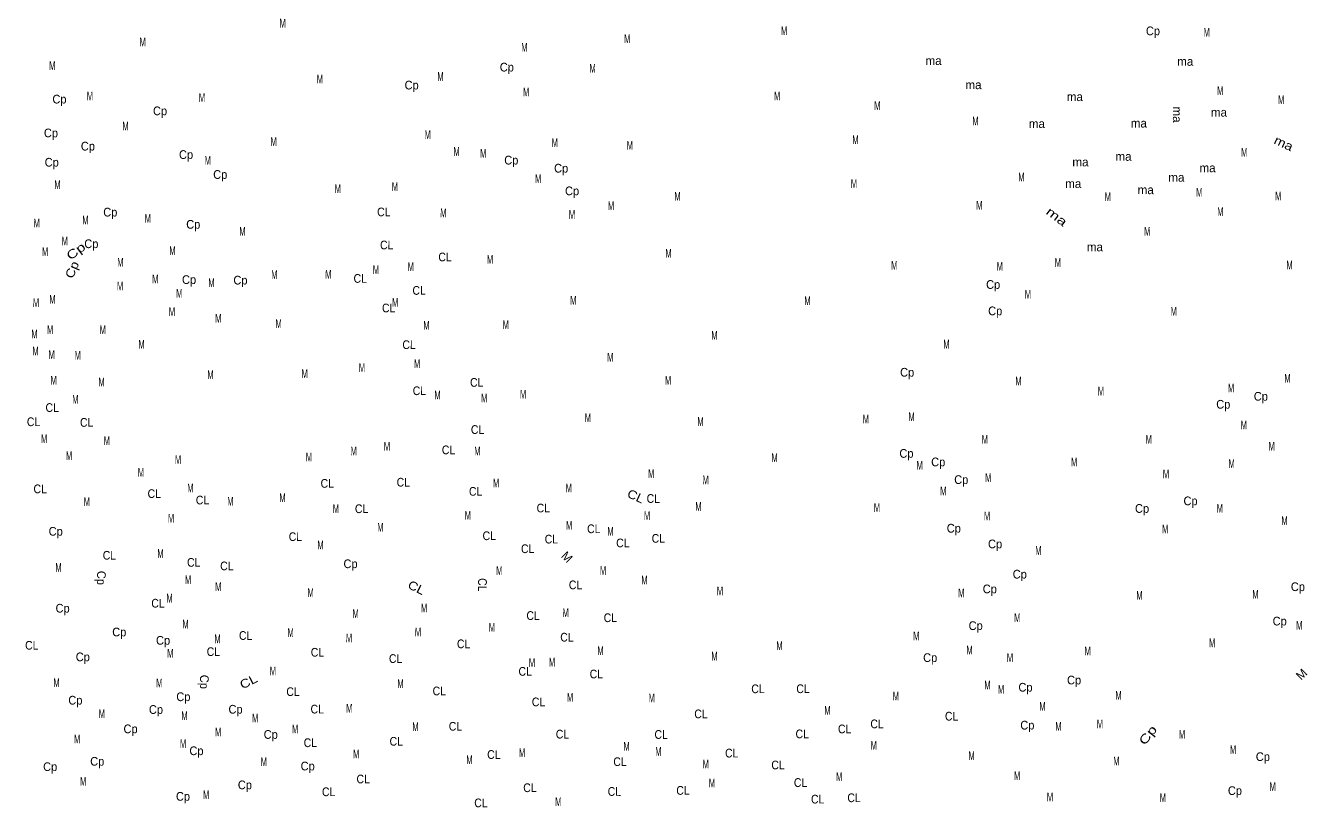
# Model space of a CAD drawing. Extents: x 713577 to 726626, y 7177731 to 7191794.
# Drawn here: x 713655 to 719260, y 7182918 to 7186338 of the extents above; entities that cross this region are included whole.
import ezdxf
from ezdxf.enums import TextEntityAlignment as Align

# ---------------------------------------------------------------- set-up
doc = ezdxf.new("R2010")
doc.units = 0
doc.header["$LTSCALE"] = 15
doc.layers.add('19', color=7, linetype='Continuous')

msp = doc.modelspace()

# ---------------------------------------------------------------- texts
at = {"layer": '19'}
for s, rotation, width, p in [('M', 359.905, 0.65, (714779.16, 7186329.35)), ('M', 359.99, 0.65, (716972.08, 7186296.01)), ('Cp', 359.99, 0.95, (718585.11, 7186295.53)), ('M', 359.99, 0.65, (718820.07, 7186289.81)), ('M', 359.905, 0.65, (714167.03, 7186247.01)), ('M', 359.905, 0.65, (716286.1, 7186261.26)), ('M', 359.905, 0.65, (715836.26, 7186223.86)), ('M', 359.905, 0.65, (713771.9, 7186143.61)), ('Cp', 359.905, 0.95, (715759.5, 7186136.98)), ('M', 359.905, 0.65, (716134.57, 7186132.32)), ('M', 359.905, 0.65, (714941.93, 7186084.8)), ('Cp', 359.905, 0.95, (715343.19, 7186058.48)), ('M', 359.905, 0.65, (715469.3, 7186096.1)), ('M', 359.905, 0.65, (713936.46, 7186010.29)), ('M', 359.905, 0.65, (714426.3, 7186003.39)), ('M', 359.905, 0.65, (715843.95, 7186028.48)), ('M', 359.99, 0.65, (716941.68, 7186011.33)), ('M', 359.99, 0.65, (718879.26, 7186034.47)), ('Cp', 359.905, 0.95, (713803.14, 7185997.05)), ('Cp', 359.905, 0.95, (714242.89, 7185945.67)), ('M', 359.99, 0.65, (717379.75, 7185968.7)), ('M', 359.99, 0.65, (719145.99, 7185994.19)), ('M', 359.99, 0.65, (717808.91, 7185901.66)), ('Cp', 359.905, 0.95, (713765.96, 7185849.13)), ('M', 359.905, 0.65, (714092.04, 7185878.92)), ('M', 359.905, 0.65, (715413.42, 7185842.1)), ('Cp', 359.905, 0.95, (713927.5, 7185791.35)), ('M', 359.905, 0.65, (714739.83, 7185811.48)), ('M', 359.905, 0.65, (715969.25, 7185806.88)), ('M', 359.905, 0.65, (716297.51, 7185795.44)), ('M', 359.99, 0.65, (717284.06, 7185819.28)), ('ma', 334.884, 1.2, (719148.78, 7185805.6)), ('Cp', 359.905, 0.95, (713769.27, 7185720.89)), ('Cp', 359.905, 0.95, (714356.7, 7185754.41)), ('M', 359.905, 0.65, (714451.49, 7185728.93)), ('M', 359.905, 0.65, (715539.82, 7185767.98)), ('M', 359.905, 0.65, (715656.29, 7185759.95)), ('Cp', 359.905, 0.95, (715779.02, 7185730.13)), ('M', 359.99, 0.65, (718984.39, 7185764.23)), ('Cp', 359.905, 0.95, (714506.27, 7185667.29)), ('Cp', 359.905, 0.95, (715996.96, 7185694.82)), ('M', 359.905, 0.65, (713794.44, 7185623.39)), ('M', 359.905, 0.65, (715270.07, 7185614.73)), ('M', 359.905, 0.65, (715896.54, 7185649.59)), ('M', 359.99, 0.65, (717277.51, 7185627.67)), ('M', 359.99, 0.65, (718009.76, 7185656.52)), ('M', 359.905, 0.65, (715020.32, 7185605.52)), ('Cp', 359.905, 0.95, (716044.88, 7185595.68)), ('M', 359.905, 0.65, (716505.91, 7185572.36)), ('M', 359.99, 0.65, (718387.53, 7185570.14)), ('M', 359.99, 0.65, (718787.63, 7185589.39)), ('M', 359.99, 0.65, (719132.95, 7185573.62)), ('Cp', 359.905, 0.95, (714025.44, 7185502.66)), ('CL', 359.905, 0.9, (715221.55, 7185503.57)), ('M', 359.905, 0.65, (715481.9, 7185499.64)), ('M', 359.905, 0.65, (716215.32, 7185530.77)), ('M', 359.99, 0.65, (717825.85, 7185532.22)), ('ma', 322.678, 1.4, (718152.62, 7185486.8)), ('M', 359.99, 0.65, (718879.81, 7185505.11)), ('M', 359.905, 0.65, (713703.75, 7185454.6)), ('M', 359.905, 0.65, (713916.64, 7185468.03)), ('M', 359.905, 0.65, (714189.47, 7185475.14)), ('Cp', 359.905, 0.95, (714388.25, 7185449.17)), ('M', 359.905, 0.65, (716044.33, 7185492.4)), ('M', 359.905, 0.65, (714603.25, 7185419)), ('M', 359.99, 0.65, (718560.15, 7185419.32)), ('M', 359.905, 0.65, (713740.42, 7185330.47)), ('M', 359.905, 0.65, (713826.41, 7185377.13)), ('Cp', 36.789, 1.35, (713886.27, 7185335.83)), ('Cp', 359.905, 0.95, (713942.44, 7185364.44)), ('M', 359.905, 0.65, (714297.27, 7185334.55)), ('CL', 359.905, 0.9, (715234.45, 7185358.96)), ('M', 359.905, 0.65, (714069.58, 7185283.31)), ('CL', 359.905, 0.9, (715489.23, 7185306.61)), ('M', 359.905, 0.65, (715686.21, 7185295.65)), ('M', 359.905, 0.65, (716466.63, 7185322.6)), ('M', 359.99, 0.65, (718169.35, 7185282.42)), ('Cp', 66.992, 1.15, (713875.77, 7185262.42)), ('M', 359.905, 0.65, (714742.93, 7185229.78)), ('M', 359.905, 0.65, (714978.98, 7185230.51)), ('M', 359.905, 0.65, (715187.07, 7185251.32)), ('M', 359.905, 0.65, (715339.32, 7185264.67)), ('M', 359.99, 0.65, (717453.85, 7185269.68)), ('M', 359.99, 0.65, (717915.16, 7185265.87)), ('M', 359.99, 0.65, (719182.26, 7185270.87)), ('M', 359.905, 0.65, (714068.11, 7185179.07)), ('M', 359.905, 0.65, (714222.37, 7185209.97)), ('Cp', 359.905, 0.95, (714369.9, 7185207.48)), ('M', 359.905, 0.65, (714467.91, 7185193.85)), ('Cp', 359.905, 0.95, (714594.62, 7185205.18)), ('CL', 359.905, 0.9, (715118.48, 7185212.65)), ('CL', 359.905, 0.9, (715376.03, 7185160.29)), ('Cp', 359.99, 0.95, (717886.24, 7185186.14)), ('M', 359.905, 0.65, (713700.63, 7185106.53)), ('M', 359.905, 0.65, (713772.49, 7185121.8)), ('M', 359.905, 0.65, (714327.1, 7185147.28)), ('M', 359.905, 0.65, (715271.29, 7185107.64)), ('M', 359.905, 0.65, (716050.35, 7185116.65)), ('M', 359.99, 0.65, (717074.13, 7185115.03)), ('M', 359.99, 0.65, (718038.37, 7185143.56)), ('M', 359.905, 0.65, (714295.16, 7185067.07)), ('CL', 359.905, 0.9, (715242.68, 7185083.44)), ('Cp', 359.99, 0.95, (717895.12, 7185070.68)), ('M', 359.99, 0.65, (718675.72, 7185068.93)), ('M', 359.905, 0.65, (714497.77, 7185037.83)), ('M', 359.905, 0.65, (714761.51, 7185014.47)), ('M', 359.905, 0.65, (715407.99, 7185007.75)), ('M', 359.905, 0.65, (715754.83, 7185010.83)), ('M', 359.905, 0.65, (713693.91, 7184969.73)), ('M', 359.905, 0.65, (713762.35, 7184989.11)), ('M', 359.905, 0.65, (713992.38, 7184988.17)), ('M', 359.905, 0.65, (716667.36, 7184964.14)), ('M', 359.905, 0.65, (713698.57, 7184895.16)), ('M', 359.905, 0.65, (714162.04, 7184925.1)), ('CL', 359.905, 0.9, (715332.12, 7184922.83)), ('M', 359.99, 0.65, (717681.88, 7184925.15)), ('M', 359.905, 0.65, (713769.01, 7184879.31)), ('M', 359.905, 0.65, (713882.9, 7184876.73)), ('M', 359.905, 0.65, (715367.18, 7184840.05)), ('M', 359.905, 0.65, (716212.06, 7184867.88)), ('M', 359.905, 0.65, (713777.71, 7184767.45)), ('M', 359.905, 0.65, (714463.47, 7184792.05)), ('M', 359.905, 0.65, (714875.43, 7184795.68)), ('M', 359.905, 0.65, (715125.96, 7184822.18)), ('Cp', 359.99, 0.95, (717510.11, 7184802.23)), ('M', 359.99, 0.65, (719173.28, 7184776.27)), ('M', 359.905, 0.65, (713987.35, 7184759.95)), ('CL', 359.905, 0.9, (715377.3, 7184721.43)), ('CL', 359.905, 0.9, (715627.85, 7184757.89)), ('M', 359.905, 0.65, (716464.71, 7184766.8)), ('M', 359.99, 0.65, (717996.78, 7184763.98)), ('M', 359.99, 0.65, (718357.6, 7184719.56)), ('M', 359.99, 0.65, (718926.8, 7184733.54)), ('M', 359.905, 0.65, (713872.66, 7184683.5)), ('M', 359.905, 0.65, (715456.32, 7184702.69)), ('M', 359.905, 0.65, (715660.62, 7184689.73)), ('M', 359.905, 0.65, (715830.41, 7184706.39)), ('Cp', 359.99, 0.95, (718892.57, 7184662.14)), ('Cp', 359.99, 0.95, (719056.78, 7184696.99)), ('CL', 359.905, 0.9, (713771.37, 7184647.75)), ('M', 359.905, 0.65, (716113.95, 7184603.27)), ('M', 359.99, 0.65, (717529.55, 7184607.96)), ('CL', 359.905, 0.9, (713689.86, 7184585.64)), ('CL', 359.905, 0.9, (713922.09, 7184582.86)), ('CL', 359.905, 0.9, (715631.49, 7184551.58)), ('M', 359.905, 0.65, (716606.27, 7184586.84)), ('M', 359.99, 0.65, (717329.7, 7184597.74)), ('M', 359.99, 0.65, (718982.39, 7184571.95)), ('M', 359.905, 0.65, (713736.25, 7184511.34)), ('M', 359.905, 0.65, (714010.2, 7184503.36)), ('M', 359.99, 0.65, (717850.06, 7184508.67)), ('M', 359.99, 0.65, (718566.64, 7184509.18)), ('M', 359.905, 0.65, (713845.23, 7184436.94)), ('M', 359.905, 0.65, (714894.09, 7184432.2)), ('M', 359.905, 0.65, (715089.81, 7184458.13)), ('M', 359.905, 0.65, (715235.36, 7184477.82)), ('CL', 359.905, 0.9, (715504.44, 7184462.75)), ('M', 359.905, 0.65, (715630.66, 7184457.56)), ('Cp', 359.99, 0.95, (717507.08, 7184447.28)), ('M', 359.99, 0.65, (719104.13, 7184478.81)), ('M', 359.905, 0.65, (714321.66, 7184420.2)), ('M', 359.99, 0.65, (716930.46, 7184428.61)), ('M', 359.99, 0.65, (717564.86, 7184394.82)), ('Cp', 359.99, 0.95, (717645.95, 7184409.98)), ('M', 359.99, 0.65, (718240.63, 7184409.85)), ('M', 359.99, 0.65, (718929.05, 7184402.82)), ('M', 359.905, 0.65, (714159.43, 7184363.91)), ('CL', 359.905, 0.9, (715306.87, 7184321.22)), ('M', 359.905, 0.65, (716390.95, 7184359.29)), ('M', 359.905, 0.65, (716629.1, 7184331.66)), ('Cp', 359.99, 0.95, (717746.68, 7184332.61)), ('M', 359.99, 0.65, (717864.82, 7184341.8)), ('M', 359.99, 0.65, (718642.09, 7184357.13)), ('CL', 359.905, 0.9, (713718.79, 7184292.13)), ('CL', 359.905, 0.9, (714217.72, 7184271.36)), ('M', 359.905, 0.65, (714375.61, 7184295.86)), ('CL', 359.905, 0.9, (714974.31, 7184316.13)), ('CL', 359.905, 0.9, (715623.07, 7184281.17)), ('M', 359.905, 0.65, (715712.49, 7184318.23)), ('M', 359.905, 0.65, (716030.39, 7184296.44)), ('CL', 335.458, 1.15, (716315.71, 7184261.85)), ('M', 359.99, 0.65, (717668.42, 7184282.32)), ('M', 359.905, 0.65, (713922.88, 7184236.38)), ('CL', 359.905, 0.9, (714428.69, 7184243.28)), ('M', 359.905, 0.65, (714550.59, 7184238.09)), ('M', 359.905, 0.65, (714778.52, 7184253.33)), ('CL', 359.905, 0.9, (715918.96, 7184208.25)), ('CL', 359.905, 0.9, (716400.08, 7184249.98)), ('M', 359.905, 0.65, (716597.35, 7184215.1)), ('M', 359.99, 0.65, (717378.12, 7184210.45)), ('Cp', 359.99, 0.95, (718537.42, 7184206.43)), ('Cp', 359.99, 0.95, (718749.35, 7184239.63)), ('M', 359.99, 0.65, (718877.35, 7184207.69)), ('M', 359.905, 0.65, (714291.12, 7184163.6)), ('M', 359.905, 0.65, (715011.99, 7184205.77)), ('CL', 359.905, 0.9, (715124.29, 7184205.25)), ('M', 359.905, 0.65, (715589, 7184176.91)), ('M', 359.905, 0.65, (716372.7, 7184175.27)), ('M', 359.99, 0.65, (717859.53, 7184173.32)), ('M', 359.99, 0.65, (719160.34, 7184153.34)), ('Cp', 359.905, 0.95, (713786.73, 7184106.52)), ('M', 359.905, 0.65, (715206.53, 7184124.38)), ('M', 359.905, 0.65, (716032.11, 7184132.65)), ('CL', 359.905, 0.9, (716139.73, 7184117.52)), ('M', 359.905, 0.65, (716212.79, 7184106.77)), ('Cp', 359.99, 0.95, (717714.18, 7184120.01)), ('M', 359.99, 0.65, (718638.76, 7184117.24)), ('CL', 359.905, 0.9, (714835.06, 7184083.14)), ('M', 359.905, 0.65, (714944.62, 7184047.08)), ('CL', 359.905, 0.9, (715682.55, 7184087.05)), ('CL', 359.905, 0.9, (715954.28, 7184072.32)), ('CL', 359.905, 0.9, (716266.87, 7184055.52)), ('CL', 359.905, 0.9, (716422.05, 7184075.53)), ('Cp', 359.99, 0.95, (717894.72, 7184051.23)), ('CL', 359.905, 0.9, (714021.69, 7184001.59)), ('M', 359.905, 0.65, (714244.69, 7184009.43)), ('CL', 359.905, 0.9, (715850.56, 7184030.3)), ('M', 359.99, 0.65, (718083.93, 7184022.56)), ('M', 359.905, 0.65, (713798.84, 7183948.23)), ('CL', 359.905, 0.9, (714390.34, 7183970.54)), ('CL', 359.905, 0.9, (714535.18, 7183955.07)), ('Cp', 359.905, 0.95, (715076.04, 7183964.47)), ('M', 359.905, 0.65, (715726.47, 7183934.82)), ('M', 359.905, 0.65, (716180.28, 7183935.07)), ('Cp', 270, 0.95, (713967.56, 7183921.7)), ('M', 359.905, 0.65, (714365.58, 7183894.65)), ('CL', 270, 0.9, (715633.95, 7183891.49)), ('CL', 359.905, 0.9, (716059.93, 7183872.15)), ('M', 359.905, 0.65, (716361.27, 7183893.24)), ('Cp', 359.99, 0.95, (718002.63, 7183918.92)), ('M', 359.905, 0.65, (714497.81, 7183863.77)), ('M', 359.905, 0.65, (714901.42, 7183838.52)), ('CL', 333.778, 1.15, (715355.93, 7183862.49)), ('M', 359.99, 0.65, (716691.58, 7183845.73)), ('M', 359.99, 0.65, (717747.13, 7183837.32)), ('Cp', 359.99, 0.95, (717871.49, 7183854.43)), ('M', 359.99, 0.65, (718525.84, 7183826.03)), ('M', 359.99, 0.65, (719033.26, 7183830.88)), ('Cp', 359.99, 0.95, (719218.86, 7183864.08)), ('Cp', 359.905, 0.95, (713816.95, 7183769.93)), ('CL', 359.905, 0.9, (714234.08, 7183791.92)), ('M', 359.905, 0.65, (714284.73, 7183814.06)), ('M', 359.905, 0.65, (715397.64, 7183770.92)), ('M', 359.905, 0.65, (715098.27, 7183746.83)), ('CL', 359.905, 0.9, (715874.33, 7183737.9)), ('M', 359.905, 0.65, (716016.86, 7183750.29)), ('CL', 359.905, 0.9, (716212.18, 7183728.37)), ('M', 359.99, 0.65, (717991.74, 7183728.39)), ('Cp', 359.99, 0.95, (719139.2, 7183713.71)), ('Cp', 359.905, 0.95, (714064.72, 7183665.94)), ('M', 359.905, 0.65, (714354.65, 7183700.39)), ('CL', 359.905, 0.9, (714617.26, 7183650.71)), ('M', 359.905, 0.65, (714813.94, 7183663.72)), ('M', 359.905, 0.65, (715371.1, 7183665.87)), ('M', 359.905, 0.65, (715694.35, 7183686.54)), ('M', 359.99, 0.65, (717550.22, 7183648.97)), ('Cp', 359.99, 0.95, (717809.77, 7183693.79)), ('M', 359.99, 0.65, (719225.09, 7183694.94)), ('CL', 359.905, 0.9, (713682.1, 7183607.85)), ('Cp', 359.905, 0.95, (714256.21, 7183629.5)), ('M', 359.905, 0.65, (714494.44, 7183636.2)), ('M', 359.905, 0.65, (715069.39, 7183639.7)), ('CL', 359.905, 0.9, (715570.43, 7183614.24)), ('CL', 359.905, 0.9, (716022.34, 7183643.31)), ('M', 359.99, 0.65, (716951.81, 7183605.87)), ('M', 359.99, 0.65, (718844.01, 7183618.66)), ('Cp', 359.905, 0.95, (713905.13, 7183557.17)), ('M', 359.905, 0.65, (714287.93, 7183572.58)), ('CL', 359.905, 0.9, (714476.23, 7183580.14)), ('CL', 359.905, 0.9, (714931.46, 7183577.33)), ('CL', 359.905, 0.9, (715273.1, 7183549.75)), ('M', 359.905, 0.65, (716169.07, 7183584.93)), ('M', 359.99, 0.65, (716667.45, 7183560.39)), ('Cp', 359.99, 0.95, (717610.83, 7183553.96)), ('M', 359.99, 0.65, (717783.1, 7183586.92)), ('M', 359.99, 0.65, (717959.79, 7183553.66)), ('M', 359.99, 0.65, (718299.39, 7183582.56)), ('M', 359.905, 0.65, (714736.7, 7183495.23)), ('CL', 359.905, 0.9, (715839.75, 7183493.74)), ('M', 359.905, 0.65, (715869.56, 7183531.66)), ('M', 359.905, 0.65, (715957.36, 7183534.12)), ('CL', 359.905, 0.9, (716150.97, 7183482.3)), ('M', 359.905, 0.65, (713790.27, 7183444.49)), ('M', 359.905, 0.65, (714239.66, 7183443.41)), ('Cp', 270, 0.95, (714417.86, 7183466.92)), ('CL', 26.919, 1.2, (714638.55, 7183451.23)), ('M', 359.905, 0.65, (715294.46, 7183440.26)), ('M', 359.99, 0.65, (717861.25, 7183433.84)), ('Cp', 359.99, 0.95, (718027.55, 7183424.32)), ('Cp', 359.99, 0.95, (718240.14, 7183455.88)), ('Cp', 359.905, 0.95, (713872.66, 7183367.66)), ('Cp', 359.905, 0.95, (714344.95, 7183382.79)), ('CL', 359.905, 0.9, (714824.46, 7183405.13)), ('CL', 359.905, 0.9, (715464.06, 7183408.17)), ('M', 359.905, 0.65, (716036.21, 7183380.2)), ('M', 359.905, 0.65, (716392.98, 7183377.92)), ('CL', 359.99, 0.9, (716857.7, 7183417.54)), ('CL', 359.99, 0.9, (717054.64, 7183417.84)), ('M', 359.99, 0.65, (717460.77, 7183385.42)), ('M', 359.99, 0.65, (717920.93, 7183415.79)), ('M', 359.99, 0.65, (718434.61, 7183389.04)), ('Cp', 359.905, 0.95, (714225.22, 7183326.98)), ('Cp', 359.905, 0.95, (714573.2, 7183328.06)), ('CL', 359.905, 0.9, (714930.36, 7183328.68)), ('M', 359.905, 0.65, (715070.59, 7183332.55)), ('CL', 359.905, 0.9, (715898.01, 7183360.25)), ('M', 359.99, 0.65, (717161.56, 7183323.12)), ('M', 359.99, 0.65, (718101.91, 7183341.06)), ('M', 359.905, 0.65, (713988.23, 7183308.61)), ('M', 359.905, 0.65, (714349.79, 7183300.06)), ('M', 359.905, 0.65, (714659.11, 7183289.2)), ('CL', 359.905, 0.9, (716608.48, 7183307.79)), ('CL', 359.99, 0.9, (717378.56, 7183264.06)), ('CL', 359.99, 0.9, (717704.49, 7183297.65)), ('Cp', 359.99, 0.95, (718035.75, 7183258.47)), ('M', 359.99, 0.65, (718353.3, 7183263.68)), ('M', 359.905, 0.65, (713880.67, 7183198.1)), ('Cp', 359.905, 0.95, (714114.06, 7183242.32)), ('M', 359.905, 0.65, (714497.15, 7183228.82)), ('Cp', 359.905, 0.95, (714727.13, 7183217.77)), ('M', 359.905, 0.65, (714833.76, 7183241.97)), ('M', 359.905, 0.65, (715359.81, 7183251.36)), ('CL', 359.905, 0.9, (715534.94, 7183253.46)), ('CL', 359.905, 0.9, (716002.78, 7183219.17)), ('CL', 359.905, 0.9, (716434.25, 7183217.72)), ('CL', 359.99, 0.9, (717051.31, 7183220.24)), ('CL', 359.99, 0.9, (717236.71, 7183241.98)), ('M', 359.99, 0.65, (718171.65, 7183253.18)), ('Cp', 51.859, 1.4, (718577.58, 7183222.16)), ('M', 359.99, 0.65, (718712.31, 7183217.88)), ('M', 359.905, 0.65, (714343.62, 7183177.44)), ('Cp', 359.905, 0.95, (714402.23, 7183146.39)), ('CL', 359.905, 0.9, (714900.36, 7183181.66)), ('CL', 359.905, 0.9, (715275.92, 7183187.88)), ('M', 359.905, 0.65, (716283.15, 7183166.37)), ('M', 359.99, 0.65, (716422.28, 7183143.29)), ('M', 359.99, 0.65, (717364.09, 7183170.51)), ('M', 359.99, 0.65, (718935.41, 7183152.02)), ('Cp', 359.905, 0.95, (713968.33, 7183100.38)), ('M', 359.905, 0.65, (714696.77, 7183098.58)), ('M', 359.905, 0.65, (715100.7, 7183132.76)), ('M', 359.905, 0.65, (715595.91, 7183106.97)), ('CL', 359.905, 0.9, (715702.68, 7183130.05)), ('M', 359.905, 0.65, (715826.15, 7183137.71)), ('CL', 359.905, 0.9, (716254.31, 7183098.7)), ('M', 359.99, 0.65, (716629.44, 7183088.17)), ('CL', 359.905, 0.9, (716743.08, 7183136.15)), ('M', 359.99, 0.65, (717791.94, 7183125.24)), ('M', 359.99, 0.65, (718425.01, 7183101.44)), ('Cp', 359.99, 0.95, (719065.72, 7183120.74)), ('Cp', 359.905, 0.95, (713762.48, 7183076.86)), ('Cp', 359.905, 0.95, (714888.63, 7183079.64)), ('CL', 359.99, 0.9, (716945.39, 7183084.35)), ('M', 359.99, 0.65, (717212.98, 7183033.3)), ('M', 359.99, 0.65, (717991.17, 7183037.78)), ('M', 359.905, 0.65, (713906.87, 7183013.13)), ('Cp', 359.905, 0.95, (714614.08, 7182997.24)), ('CL', 359.905, 0.9, (715131.31, 7183022.92)), ('CL', 359.905, 0.9, (715860.45, 7182984.77)), ('M', 359.905, 0.65, (716656.35, 7183005.83)), ('CL', 359.99, 0.9, (717044.01, 7183007.47)), ('M', 359.99, 0.65, (719108.47, 7182990.09)), ('Cp', 359.905, 0.95, (714343.24, 7182946.98)), ('M', 359.905, 0.65, (714444.66, 7182953.91)), ('CL', 359.905, 0.9, (714980.25, 7182967.07)), ('CL', 359.905, 0.9, (715646.23, 7182918.43)), ('M', 359.905, 0.65, (715984.5, 7182923.34)), ('CL', 359.905, 0.9, (716229.81, 7182968.42)), ('CL', 359.905, 0.9, (716529.78, 7182973.06)), ('CL', 359.99, 0.9, (717118.88, 7182934.88)), ('CL', 359.99, 0.9, (717277.89, 7182940.79)), ('M', 359.99, 0.65, (718134.74, 7182944.19)), ('M', 359.99, 0.65, (718628.35, 7182941.14)), ('Cp', 359.99, 0.95, (718943.54, 7182972.08))]:
    msp.add_text(s, height=38, rotation=rotation, dxfattribs=dict(at, width=width)).set_placement(p, align=Align.CENTER)
for s, rotation, p in [('ma', 359.99, (717625.61, 7186165.39)), ('ma', 359.99, (718726.32, 7186162.07)), ('ma', 359.99, (717800.09, 7186059.8)), ('ma', 359.99, (718243.44, 7186007.6)), ('ma', 270, (718672.39, 7185948.75)), ('ma', 359.99, (718873.71, 7185939.59)), ('ma', 359.99, (718077.36, 7185889.74)), ('ma', 359.99, (718523.24, 7185891.94)), ('ma', 359.99, (718456.08, 7185746.5)), ('ma', 359.99, (718267.85, 7185722.18)), ('ma', 359.99, (718823.97, 7185696.42)), ('ma', 359.99, (718236.57, 7185627.42)), ('ma', 359.99, (718687.4, 7185654.98)), ('ma', 359.99, (718553.46, 7185600.38)), ('ma', 359.99, (718331.07, 7185350.47)), ('M', 315, (716008.92, 7183999.6)), ('M', 44.119, (719248.04, 7183486.47))]:
    msp.add_text(s, height=38, rotation=rotation, dxfattribs=at).set_placement(p, align=Align.CENTER)

doc.saveas('drawing.dxf')
